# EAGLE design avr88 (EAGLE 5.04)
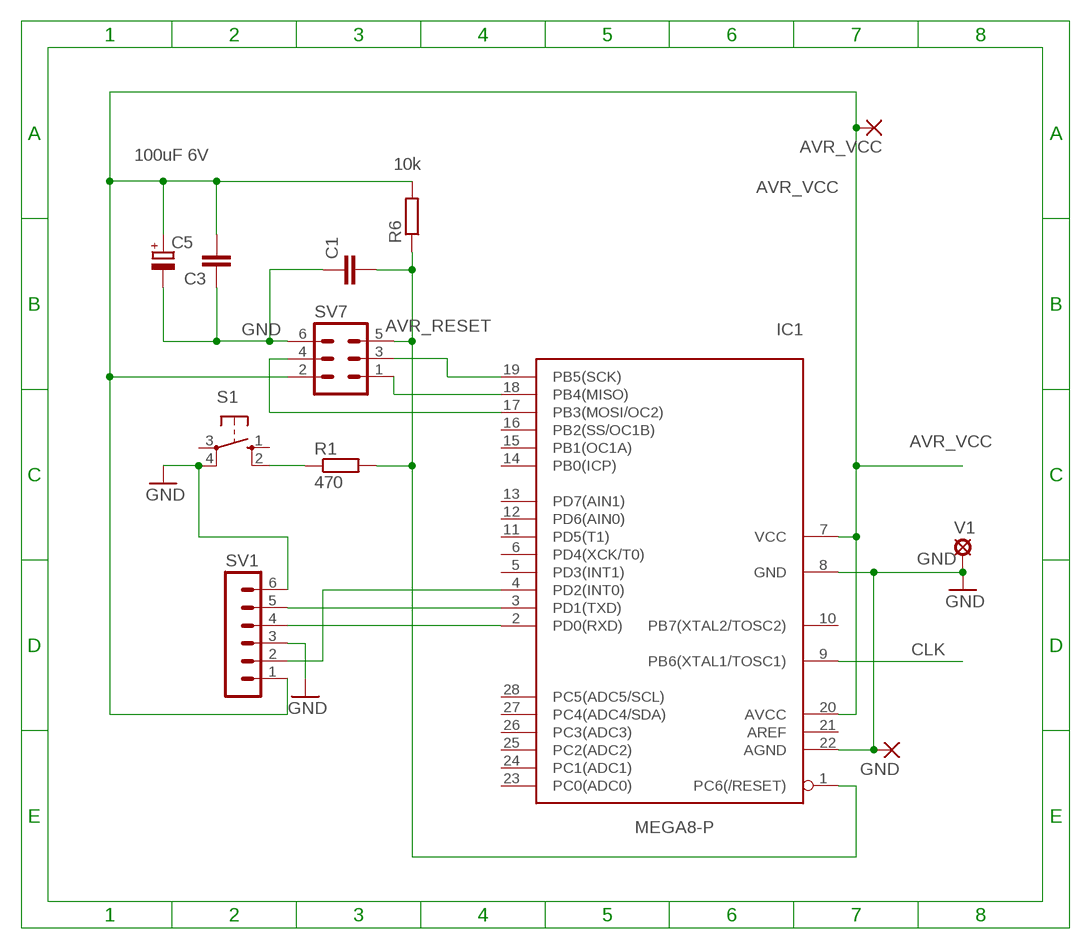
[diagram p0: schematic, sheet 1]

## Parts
AVR_VCC  PAD-TERMINAL  [2,54/1,1]
C1  C5P  [C050-030-075]
C3  C5P  [C050-030-075]
C5  100uF 6V  CPOL1  [E2,5-7---100UF]
GND  PAD-TERMINAL  [2,54/1,1]
IC1  MEGA8-P  [DIL28-3]
R1  470  R  [0207/10]
R6  10k  R  [0207/10]
S1  10-XX  [B3F-10XX]
SV1  MA06-1  [MA06-1]
SV7  ML6  [ML6]
V1  HOLE-VIA  [LSP10]

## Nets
AVR_RESET: C1.2 IC1.1(PC6(/RESET)) R1.2 R6.1 SV7.5
AVR_VCC: AVR_VCC.1(P) C3.2 C5.+ IC1.7(VCC) IC1.20(AVCC) R6.2 SV1.1 SV7.2
CLK: IC1.9(PB6(XTAL1/TOSC1))
GND [supply]: C1.1 C3.1 C5.- GND.1(P) IC1.8(GND) IC1.22(AGND) S1.4(P1) SV1.3 SV1.6 SV7.6 V1.MP
N$1: R1.1 S1.2(S1)
N$2: IC1.19(PB5(SCK)) SV7.3
N$3: IC1.18(PB4(MISO)) SV7.1
N$4: IC1.3(PD1(TXD)) SV1.5
N$5: IC1.2(PD0(RXD)) SV1.4
N$6: IC1.4(PD2(INT0)) SV1.2
N$8: IC1.17(PB3(MOSI/OC2)) SV7.4
Unconnected: IC1.5(PD3(INT1)) IC1.6(PD4(XCK/T0)) IC1.10(PB7(XTAL2/TOSC2)) IC1.11(PD5(T1)) IC1.12(PD6(AIN0)) IC1.13(PD7(AIN1)) IC1.14(PB0(ICP)) IC1.15(PB1(OC1A)) IC1.16(PB2(SS/OC1B)) IC1.21(AREF) IC1.23(PC0(ADC0)) IC1.24(PC1(ADC1)) IC1.25(PC2(ADC2)) IC1.26(PC3(ADC3)) IC1.27(PC4(ADC4/SDA)) IC1.28(PC5(ADC5/SCL)) S1.1(S) S1.3(P)

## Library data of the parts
AVR_VCC GND = ee2parts:PAD-TERMINAL: LARGE THROUGH-HOLE PAD
C1 C3 = ee2parts:C: Capacitor
C5 = ee2parts:CPOL: Electrolytic (polarised) capacitor
IC1 = atmel:MEGA8-P: MICROCONTROLLER 8 Kbytes FLASH, 1 kbytes SRAM, 512 bytes EEPROM, USART, 4-channel 10 bit ADC, 2-channel 8 bit ADC Pin compatible with Atmega48, ATMega88, ATMega168 Source: avr.lbr
R1 R6 = ee2parts:R: Resistor
S1 = switch-omron:10-XX: OMRON SWITCH
SV1 = con-lstb:MA06-1: PIN HEADER
SV7 = con-harting-ml:ML6: HARTING
V1 = ee2parts:HOLE-VIA: FIXED VIA

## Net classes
1 supply: width 0.635 mm

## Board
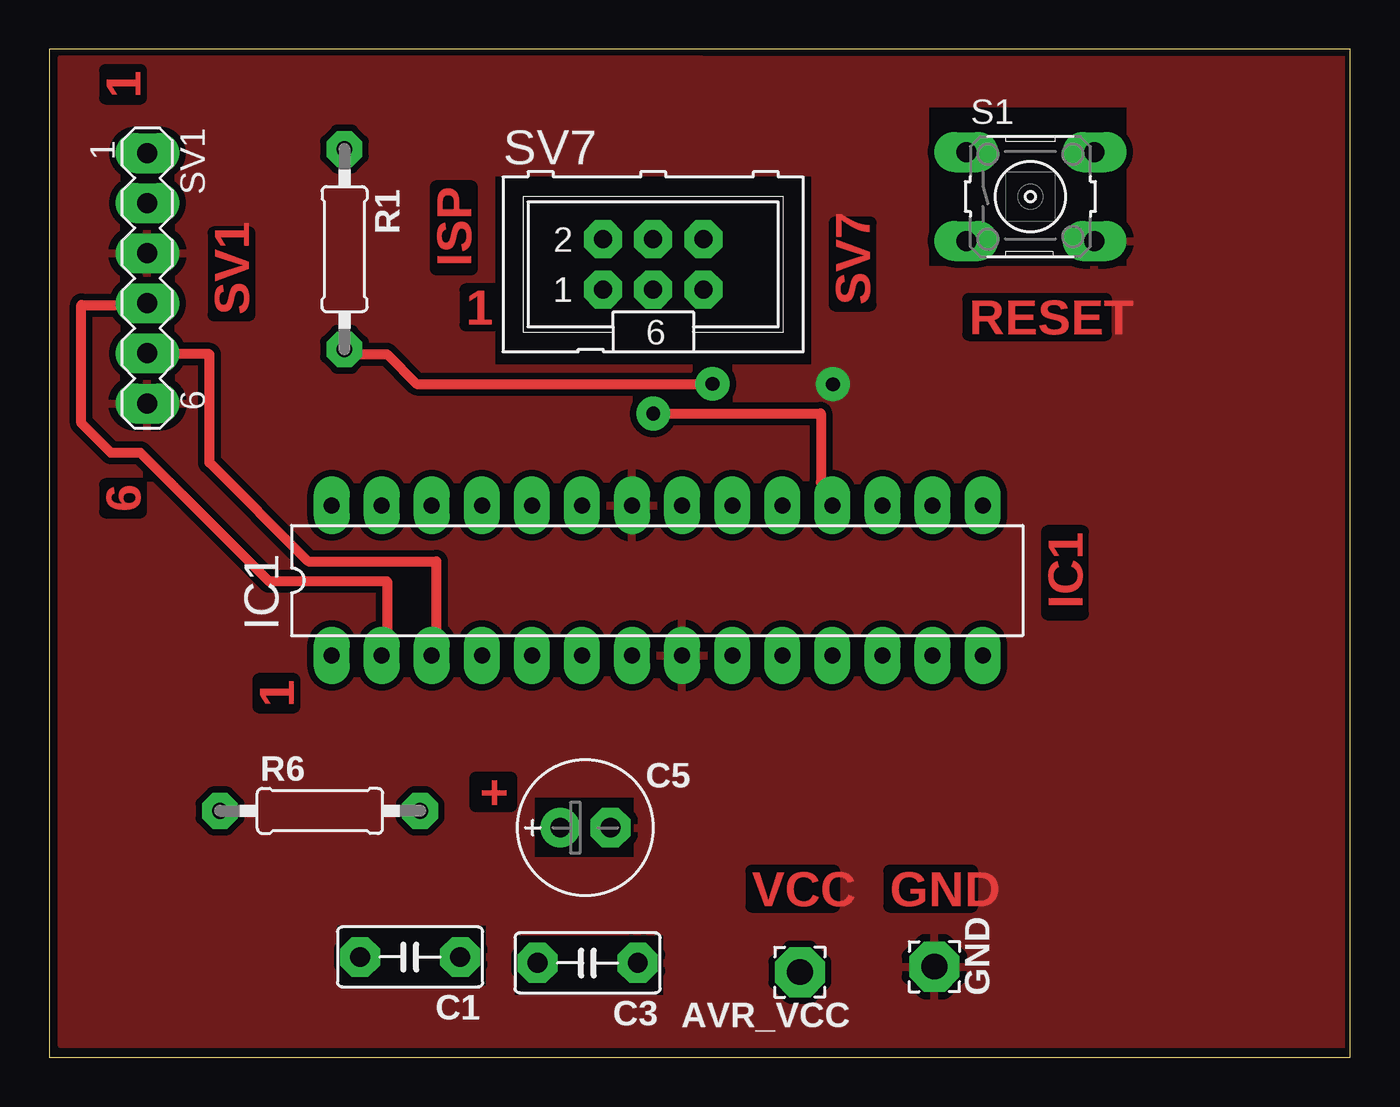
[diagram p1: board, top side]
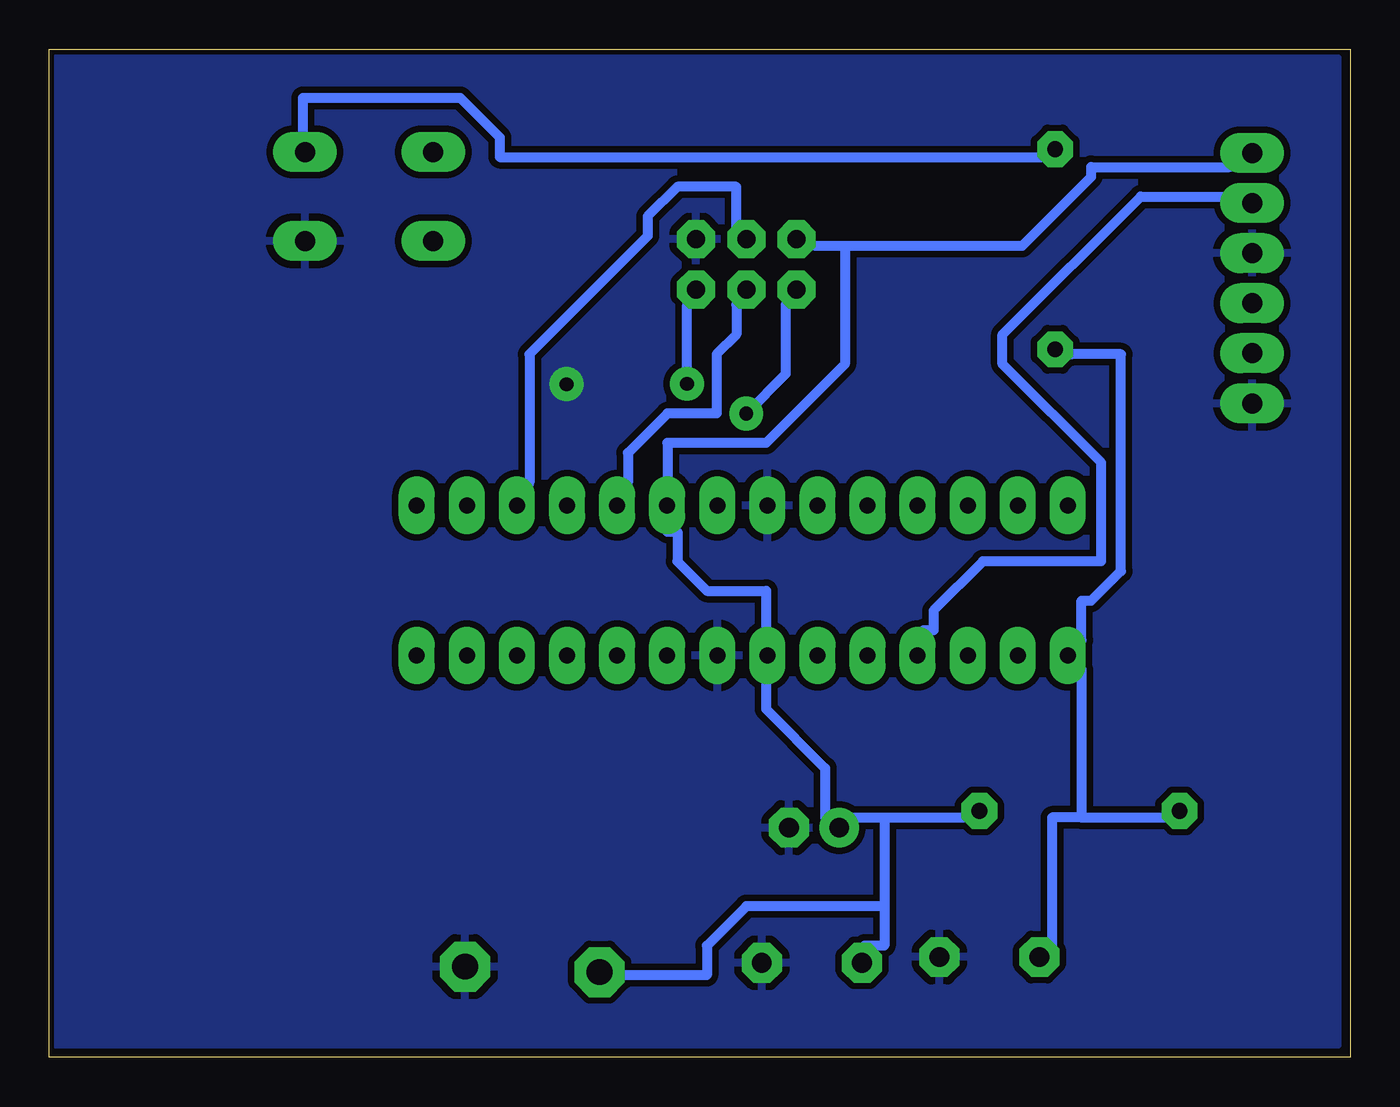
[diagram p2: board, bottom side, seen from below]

Size 65.98 x 51.13 mm. Coordinates in mm from the lower left corner, seen from the top.
Outline: 0,51.13 0,0 65.98,0 65.98,51.13 0,51.13
Copper layers (1*16): Top 0.035mm / dielectric 1.5mm / Bottom 0.035mm
Design rules "zigbit_rules *": minimum track width 20mil, minimum drill 0.7mm, track to track 13mil, track to pad 13mil, pad to pad 13mil, via to via 13mil, smd to smd 0mil, copper to edge 10mil, drill to drill 10mil, minimum pad ring 20mil, minimum via ring 20mil, stop-mask expansion 0mil, vias tented up to drill 0mil, thermal gap 15mil
tRestrict: area 24.6,10.2 to 29.6,13.2; area 14.6,3.7 to 22.1,6.7; area 23.6,3.2 to 31.1,6.2; area 22.6,35.2 to 38.6,44.7; area 44.6,40.2 to 54.6,48.2

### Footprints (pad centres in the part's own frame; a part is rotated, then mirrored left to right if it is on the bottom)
2,54/1,1 = drill 1.3 pad 2.54 octagon: 1 0,0
C050-030-075 = drill 1 octagon: 1 -2.54,0; 2 2.54,0
E2,5-7---100UF = drill 1 pad 1.6 round: + -1.27,0 | drill 1 pad 1.6 octagon: - 1.27,0
DIL28-3 = drill 0.813 long: 1 -16.51,-3.81; 2 -13.97,-3.81; 3 -11.43,-3.81; 4 -8.89,-3.81; 5 -6.35,-3.81; 6 -3.81,-3.81; 7 -1.27,-3.81; 8 1.27,-3.81; 9 3.81,-3.81; 10 6.35,-3.81; 11 8.89,-3.81; 12 11.43,-3.81; 13 13.97,-3.81; 14 16.51,-3.81; 15 16.51,3.81; 16 13.97,3.81; 17 11.43,3.81; 18 8.89,3.81; 19 6.35,3.81; 20 3.81,3.81; 21 1.27,3.81; 22 -1.27,3.81; 23 -3.81,3.81; 24 -6.35,3.81; 25 -8.89,3.81; 26 -11.43,3.81; 27 -13.97,3.81; 28 -16.51,3.81
0207/10 = drill 0.8 octagon: 1 -5.08,0; 2 5.08,0
B3F-10XX = drill 1.016 long: 1 -3.251,2.261; 2 3.251,2.261; 3 -3.251,-2.261; 4 3.251,-2.261
MA06-1 = drill 1.016 long: 1 -6.35,0; 2 -3.81,0; 3 -1.27,0; 4 1.27,0; 5 3.81,0; 6 6.35,0
ML6 = drill 0.914 octagon: 1 -2.54,-1.27; 2 -2.54,1.27; 3 0,-1.27; 4 0,1.27; 5 2.54,-1.27; 6 2.54,1.27
LSP10 = drill 0.7 pad 1.016 round: MP 0,0

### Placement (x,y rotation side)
AVR_VCC  38.07,4.32 180 top
C1  18.3,5.09 180 top
C3  27.3,4.79 180 top
C5  27.19,11.65 0 top
GND  44.89,4.6 270 top
IC1  30.83,24.19 0 top
R1  14.97,40.99 270 top
R6  13.73,12.5 0 top
S1  49.76,43.66 0 top
SV1  4.97,39.52 270 top
SV7  30.63,40.22 0 top
V1  39.74,34.14 270 top

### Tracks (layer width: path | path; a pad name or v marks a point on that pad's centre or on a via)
AVR_RESET  (via drill 0.7)
  Top 0.508: v33.63,34.16 18.63,34.16 17.13,35.66 15.63,35.66 R1.2
  Bottom 0.508: 13.63,12.16 15.13,12.16 15.13,5.66 C1.2 | 13.63,12.16 9.13,12.16 R6.1 | R1.2 14.13,35.66 11.63,35.66 11.63,24.66 13.13,23.16 13.63,23.16 13.63,21.16 IC1.1 13.63,19.66 13.63,12.16 | v33.63,34.16 33.63,38.16 SV7.5
AVR_VCC
  Bottom 0.508: 23.63,12.16 25.13,12.16 C5.+ 26.63,12.16 26.63,14.66 29.63,17.66 29.63,19.16 IC1.7 29.63,21.66 29.63,23.66 32.63,23.66 34.13,25.16 34.13,26.66 34.63,26.66 IC1.20 34.63,29.16 34.63,31.16 29.63,31.16 25.63,35.16 25.63,41.16 | 23.63,12.16 19.63,12.16 R6.2 | 23.63,12.16 23.63,7.66 | 23.63,7.66 23.63,5.66 24.63,5.66 C3.2 | 23.63,7.66 30.63,7.66 32.63,5.66 32.63,4.16 37.13,4.16 AVR_VCC.1 | 25.63,41.16 27.13,41.16 SV7.2 | 25.63,41.16 16.63,41.16 13.13,44.66 13.13,45.16 6.13,45.16 SV1.1
GND
  pour Top: 65.63,50.6 65.63,0.66 0.63,0.66 0.63,50.66
  pour Bottom: 65.63,50.66 65.63,0.66 0.63,0.66 0.63,50.66
N$1
  Bottom 0.508: R1.1 15.63,45.66 43.13,45.66 43.13,46.66 45.13,48.66 53.13,48.66 53.13,46.66 S1.2
N$2
  Bottom 0.508: IC1.19 36.63,29.16 36.63,30.66 34.63,32.66 32.13,32.66 32.13,35.66 31.13,36.66 31.13,38.16 SV7.3
N$3  (via drill 0.7)
  Top 0.508: v30.63,32.66 39.13,32.66 39.13,29.16 IC1.18
  Bottom 0.508: v30.63,32.66 28.63,34.66 28.63,38.16 SV7.1
N$4
  Top 0.508: IC1.3 19.63,21.66 19.63,25.16 13.13,25.16 8.13,30.16 8.13,35.66 6.13,35.66 SV1.5
N$5
  Top 0.508: IC1.2 17.13,21.66 17.13,24.16 11.13,24.16 4.63,30.66 3.13,30.66 1.63,32.16 1.63,38.16 3.63,38.16 SV1.4
N$6
  Bottom 0.508: IC1.4 21.63,21.66 21.13,21.66 21.13,22.66 18.63,25.16 12.63,25.16 12.63,30.16 17.63,35.16 17.63,36.66 10.63,43.66 6.13,43.66 SV1.2
N$8
  Bottom 0.508: IC1.17 41.63,29.16 41.63,35.66 35.63,41.66 35.63,42.66 34.13,44.16 31.13,44.16 31.13,42.16 SV7.4

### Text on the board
Top: 1 | ISP | SV7 | SV1 | 1 | RESET | 6 | IC1 | 1 | + | VCC | GND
